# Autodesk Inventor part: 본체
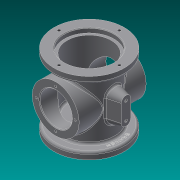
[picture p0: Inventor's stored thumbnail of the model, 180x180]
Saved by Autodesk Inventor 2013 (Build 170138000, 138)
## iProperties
Created: 2018-02
Part Number: 본체
Material: 일반
Document SubType Name: Modeling
Designer: Administrator
Density: 1 g/cm^3
Author: Administrator
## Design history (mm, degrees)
sketch "스케치5"
  geometry: C1 r 38 at (0, 0); 1 further point
  constraints: 1 centre point, 1 coincident
  dimensions: "d5" = 76 diameter of C1
extrude "돌출2" new body sketch "스케치5" distance "d6" = 108; taper "d7" = 0 deg
sketch "스케치6"
  geometry: C1 r 52.5 at (0, 0); C2 r 38 at (0, 0); 1 further point
  constraints: 2 centre point, 2 coincident
  dimensions: "d9" = 105 diameter of C1; "d10" = 76 diameter of C2
extrude "돌출3" join sketch "스케치6" distance "d11" = 10; taper "d12" = 0 deg
node "작업 평면1"
sketch "스케치7"
  geometry: C1 r 52.5 at (0, 0) reference; C2 r 34 at (0, 0)
  constraints: 1 centre point, 1 coincident
  dimensions: "d14" = 68 diameter of C2
extrude "돌출4" cut sketch "스케치7" distance "d15" = 16; taper "d16" = 0 deg
sketch "스케치8"
  geometry: C1 r 52.5 at (0, 0) reference; C2 r 37 at (0, 0)
  constraints: 1 centre point, 1 coincident
  dimensions: "d17" = 74 diameter of C2
extrude "돌출5" cut sketch "스케치8" distance "d19" = 7; taper "d20" = 0 deg
sketch "스케치9"
  geometry: C1 r 37 at (0, 0) reference; C2 r 33 at (0, 0)
  constraints: 1 centre point, 1 coincident
  dimensions: "d22" = 66 diameter of C2
extrude "돌출6" cut sketch "스케치9" distance "d23" = 79; taper "d24" = 0 deg
node "작업 평면2"
sketch "스케치10"
  geometry: L1 (34, 0)-(-34, 0) reference; L2 (0, 0)-(0, 54); C1 r 35 at (0, 54)
  constraints: 2 end point, 1 centre point, 1 coincident, 1 perpendicular
  dimensions: "d26" = 54 distance of L2.start L2.end; "d27" = 70 diameter of C1
extrude "돌출7" join sketch "스케치10" stored distance "d28" = 79; taper "d29" = 0 deg
sketch "스케치11"
  geometry: C1 r 35 at (0, 0) reference; 2 further points
  constraints: 1 vertical alignment
  dimensions: "d30" = 29 distance of C1.centre point (0, 29)
hole "구멍1" sketch "스케치11" at (0, 29) diameter "d31" = 3.242; stored, may be unused: countersink angle "d35" = 90 deg, drill point angle "d37" = 118 deg; dims "d32" = 4, "d33" = 4, "d34" = 2, "d36" = 6
sketch "스케치12"
  geometry: C1 r 35 at (0, 0) reference; C2 r 24 at (0, 0); 1 further point
  constraints: 1 centre point, 1 coincident
  dimensions: "d41" = 48 diameter of C2
extrude "돌출9" cut sketch "스케치12" stored distance "d44" = 79; taper "d45" = 0 deg
sketch "스케치13"
  geometry: L1 (35, 50)-(-35, 50) reference; L2 (35, -50)-(-35, -50) reference; C1 r 33 at (0, 0) reference; C2 r 5 at (0, 0)
  constraints: 1 centre point, 1 coincident
  dimensions: "d46" = 10 diameter of C2
extrude "돌출10" cut sketch "스케치13" stored distance "d47" = 79; taper "d48" = 0 deg
node "작업 평면3"
sketch "스케치18"
  geometry: L1 (0, 0)-(54, 0); L2 (54, 0)-(54, -7); L3 (54, -7)-(41, -7); L4 (41, 0)-(41, 7); L5 (41, 7)-(67, 7); L6 (67, 7)-(67, 0); L7 (67, -7)-(41, -7); A1 r 7 centre (41, 0) between (41, 7) and (41, -7); A2 r 7 centre (67, 0) between (67, -7) and (67, 7)
  constraints: 14 end point, 4 perpendicular, 4 point on circle, 2 centre point, 2 point on line, 1 horizontal, 1 parallel, 1 tangent
  dimensions: "d77" = 54 distance of L1.start L1.end; "d78" = 7 distance of L1.end L2.end; "d79" = 13 distance of L2.end L3.end; "d80" = 14 distance of L4.end L3.end; "d81" = 26 distance of L4.end L5.end; "d82" = 14 distance of L5.end L7.start
extrude "돌출14" join sketch "스케치18" stored distance "d83" = 79; taper "d84" = 15 deg
sketch "스케치20"
  geometry: A1 r 7 centre (0, 41) between (-7, 41) and (7, 41) reference; A2 r 7 centre (0, 67) between (7, 67) and (-7, 67) reference; 3 further points
  constraints: 2 coincident
hole "구멍2" sketch "스케치20" at (0, 67), (0, 41) diameter "d85" = 4.134; stored, may be unused: countersink angle "d89" = 90 deg, drill point angle "d91" = 118 deg; dims "d86" = 6, "d87" = 4, "d88" = 2, "d90" = 8
sketch "스케치21"
  geometry: C1 r 37 at (0, 0) reference; 1 further point
  constraints: 1 vertical alignment
  dimensions: "d92" = 45 distance of C1.centre point (0, 45)
hole "구멍3" sketch "스케치21" at (0, 45) diameter "d93" = 4.134; stored, may be unused: countersink angle "d97" = 90 deg, drill point angle "d99" = 118 deg; dims "d94" = 4, "d95" = 4, "d96" = 2, "d98" = 6
sketch "스케치22"
  geometry: C1 r 52.5 at (0, 0) reference; C2 r 43 at (0, 0)
  constraints: 1 centre point, 1 coincident, 1 other
  dimensions: "d103" = 86 diameter of C2
feature "엠보싱1" sketch "스케치22" dims "d6" = 108, "d17" = 74, "d104" = 0.5, "d105" = 0
chamfer "모따기1" distance "d106" = 1; stored, may be unused: second distance "d107" = 2, angle "d108" = 45 deg
fillet "모깎기1" dims "d109" = 3
fillet "모깎기2" dims "d110" = 3
fillet "모깎기3" dims "d111" = 3
fillet "모깎기4" dims "d112" = 3
fillet "모깎기5" dims "d113" = 3
fillet "모깎기6" dims "d114" = 3
node "솔리드2"
mirror "대칭1"
pattern_circular "원형 패턴1" dims angle "d39" = 360 deg
mirror "대칭3"
pattern_circular "원형 패턴2" dims angle "d101" = 360 deg
other parameters: "d13" = 54, "d49" = 55
